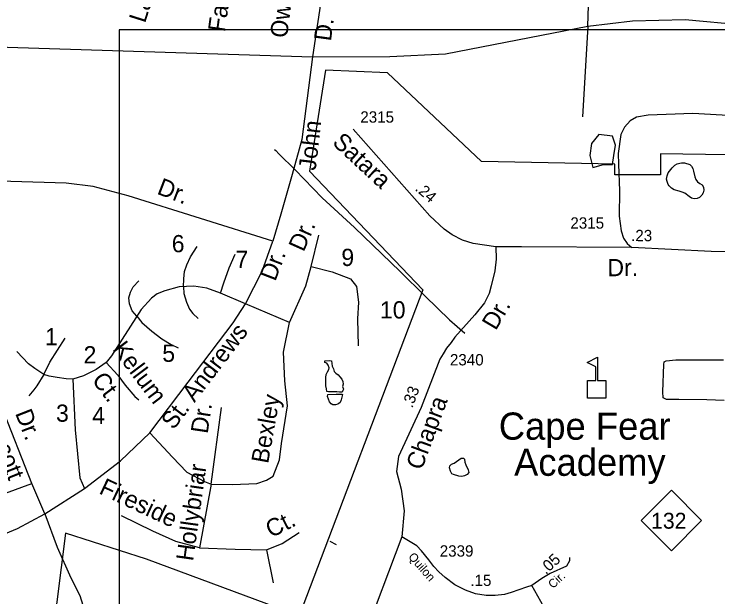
# Model space of a CAD drawing. Extents: x 2290055 to 2389491, y 66597 to 237875.
# Drawn here: x 2331332 to 2335214, y 153632 to 156845 of the extents above; entities that cross this region are included whole.
import ezdxf

# ---------------------------------------------------------------- set-up
doc = ezdxf.new("R2010")
doc.units = 0
for name, color, linetype in [('Exist Boundary Political City Limit New', 7, 'Continuous'), ('Exist Cultural Educational Facility Elementary CELL', 7, 'Continuous'), ('Exist Cultural Educational Facility Elementary Label', 7, 'Continuous'), ('Exist Hydrographic Pond Under 1500 Sq Ft', 7, 'Continuous'), ('Exist Road Non-System Type 51', 7, 'Continuous'), ('Exist Road Non-System Type 51 Label', 7, 'Continuous'), ('Exist Road Primary NC Shield CELL', 7, 'Continuous'), ('Exist Road Primary NC Shield Number Label', 7, 'Continuous'), ('Exist Road Secondary Mileage Hundredths English Label', 7, 'Continuous'), ('Exist Road Secondary Type 51 Attributed', 7, 'Continuous'), ('Exist Road Secondary Type 51 Label', 7, 'Continuous'), ('Exist Road Secondary Type 51 Number Label', 7, 'Continuous'), ('Map Preparation Boundary City Limit Buffer Line', 7, 'Continuous'), ('Map Preparation Inset Cut Line', 7, 'Continuous')]:
    doc.layers.add(name, color=color, linetype=linetype)

msp = doc.modelspace()

# ---------------------------------------------------------------- linework, layer by layer
at = {"layer": 'Exist Boundary Political City Limit New'}
msp.add_lwpolyline([(2335517.8, 156066.1), (2334898, 156075.8), (2334898, 155959.5), (2334646.2, 155959.5), (2334646.2, 156017.7), (2333910.5, 156032.2), (2333392.5, 156521.3), (2333049, 156535.9), (2332961.8, 155978.9), (2333586.2, 155325.1), (2332904, 153527.9), (2332062.8, 153841.3), (2331615.2, 153984.5), (2331473, 152848.5), (2331042.8, 151629.8), (2330040.5, 150815.1)], dxfattribs=at)
at = {"layer": 'Exist Cultural Educational Facility Elementary CELL'}
msp.add_lwpolyline([(2334494.6, 154727.8), (2334494.6, 154825.8), (2334540.6, 154825.8), (2334540.6, 154900.9), (2334493.6, 154925.1), (2334550.2, 154954.3), (2334550.2, 154825.8), (2334596.3, 154825.8), (2334596.3, 154727.8)], close=True, dxfattribs=at)
at = {"layer": 'Exist Hydrographic Pond Under 1500 Sq Ft'}
for points in [[(2334649.1, 156123.4), (2334632.6, 156173), (2334558.4, 156181.2), (2334517.1, 156131.7), (2334508.8, 156065.6), (2334525.3, 155999.5), (2334583.1, 156016), (2334632.6, 156016), (2334640.9, 156065.6), (2334649.1, 156123.4)], [(2335083.7, 155827.3), (2335069, 155831.2), (2335056, 155839.5), (2335032, 155858.6), (2335017.7, 155864.6), (2335000, 155869.9), (2334972.5, 155877.3), (2334958.2, 155884.9), (2334945, 155898.4), (2334939.7, 155906.1), (2334934.2, 155921.9), (2334931.5, 155935.8), (2334933.7, 155954.1), (2334940.2, 155969.4), (2334961.2, 155997.7), (2334976.7, 156011.7), (2334990.5, 156019.3), (2335004.2, 156023.8), (2335014.2, 156025.7), (2335030.2, 156024.7), (2335059.7, 156015.6), (2335069, 156007.8), (2335075.2, 155993.8), (2335080, 155978.9), (2335087.7, 155948.7), (2335093.5, 155934.1), (2335102.7, 155921.3), (2335114.5, 155911.6), (2335127.7, 155904.7), (2335135.5, 155891.3), (2335136, 155875.3), (2335132.2, 155860.3), (2335125.2, 155846.4), (2335113.2, 155835.1), (2335099.5, 155828.8), (2335083.7, 155827.3)], [(2333127, 154760.9), (2333112, 154762.7), (2333096.2, 154763), (2333066, 154762.3), (2333056.5, 154764.3), (2333055, 154780.1), (2333052.5, 154795.6), (2333051.2, 154826.8), (2333051.5, 154841.9), (2333053.2, 154857.8), (2333060, 154872.4), (2333068.2, 154885.4), (2333069.5, 154895.7), (2333064.5, 154910.2), (2333057, 154920.9), (2333046.7, 154924.2), (2333047, 154934), (2333074, 154935.7), (2333082.5, 154933.6), (2333085.5, 154918.7), (2333087, 154903.7), (2333093.7, 154889.2), (2333098, 154874.7), (2333106.7, 154865.8), (2333120, 154857.1), (2333129, 154844.8), (2333140, 154833.2), (2333146, 154820.1), (2333146.5, 154805.7), (2333144, 154793.1), (2333148.5, 154778.5), (2333145.7, 154769.4), (2333142.2, 154761.3), (2333127, 154760.9)], [(2333090.5, 154691), (2333080.5, 154697.4), (2333071.5, 154708.6), (2333061.7, 154737.6), (2333062.2, 154747.8), (2333108.7, 154749.5), (2333139.2, 154749.8), (2333144, 154748.6), (2333136.2, 154719.2), (2333131, 154705), (2333124.2, 154698.5), (2333117.2, 154694.6), (2333105.5, 154691.5), (2333090.5, 154691)], [(2333801, 154296.1), (2333785, 154298.5), (2333755.2, 154306.4), (2333746.7, 154310.6), (2333739, 154324.9), (2333733.5, 154343.2), (2333736.5, 154354.7), (2333745.7, 154364.1), (2333760, 154370.1), (2333784.7, 154388.8), (2333797.5, 154397), (2333811, 154398), (2333816.5, 154391.2), (2333818.7, 154375.8), (2333824.5, 154360.8), (2333837, 154332.5), (2333840.7, 154317.7), (2333830.5, 154306.4), (2333816.5, 154299.1), (2333801, 154296.1)]]:
    msp.add_lwpolyline(points, dxfattribs=at)
at = {"layer": 'Exist Road Non-System Type 51'}
for p, q in [((2332883.4, 155987.2), (2332793.2, 156075.3)), ((2333073.8, 153939.6), (2333109.2, 153921.2))]:
    msp.add_line(p, q, dxfattribs=at)
for points in [[(2329074.5, 157614.2), (2329735.5, 156994.4), (2329904, 156887), (2330064.9, 156787.4), (2330306.6, 156694.5), (2332978.6, 156610), (2333405, 156611), (2333711.5, 156626.4), (2334109.8, 156703), (2334497.5, 156778.2), (2334742.6, 156808.8), (2335033.7, 156816.5), (2335352.2, 156786.3)], [(2334497.5, 156778.2), (2334520.5, 157529.5)], [(2333057, 157134.9), (2332978.6, 156610), (2332918.7, 156153.4), (2332866.5, 155960.4), (2332804, 155743.1), (2332759.4, 155594.3), (2331962, 155844.3), (2331768.6, 155894.9), (2331619.9, 155912.8), (2331313.4, 155921.7), (2331161.7, 155930.7), (2331087.3, 155933.6), (2331012.9, 155972.3), (2330890.7, 156047.3), (2330775.5, 156052), (2330591.1, 155913.6), (2330489.7, 155821.3)], [(2334497.5, 156778.2), (2334466.8, 156279.9)], [(2335278.5, 156285.5), (2335238.5, 156288.1), (2335076, 156297.8), (2334928.2, 156291.9), (2334830.3, 156288), (2334764.7, 156277.6), (2334729.8, 156256.2), (2334698.9, 156222.8), (2334678.6, 156181.9), (2334664.6, 156077.3), (2334666.4, 156017.7)], [(2332768.7, 156098.4), (2332775.2, 156092.9), (2332793.2, 156075.3)], [(2334666.4, 156017.7), (2334670.8, 155871.8), (2334670.4, 155731.7), (2334681.5, 155650), (2334693.3, 155610.5), (2334714.5, 155581.4), (2334739.3, 155558.1)], [(2333599.2, 155291.2), (2333462, 155425.6), (2333360.2, 155523.6), (2333210.5, 155668), (2333031.7, 155832.9), (2332883.4, 155987.2)], [(2331501.7, 154089.6), (2331429.5, 154258), (2331261.8, 154683.9), (2331192.4, 154818.2), (2331128.2, 154906.2), (2330945.4, 155182.8), (2330734, 155541.8), (2330595.8, 155703.3), (2330489.7, 155821.3)], [(2332761.3, 154298.8), (2332796.6, 154388.6), (2332807, 154477.9), (2332839.7, 154686.3), (2332824.8, 154823.2), (2332818.9, 154981), (2332851.6, 155144.7), (2332940.9, 155347.2), (2332970.6, 155454.3), (2333012.3, 155627)], [(2330961.4, 153779.9), (2331082.5, 153881.8), (2331204.1, 153948.8), (2331351.6, 154008.7), (2331501.7, 154089.6), (2331719.9, 154230.2), (2331918.5, 154382.3), (2332081, 154537.4), (2332291.5, 154815.8), (2332539.9, 155143.3), (2332608.4, 155248.9), (2332699.9, 155427.6), (2332759.4, 155594.3)], [(2332266.4, 155342.5), (2332267.7, 155385.9), (2332272.2, 155426.1), (2332284.1, 155463.3), (2332304.9, 155506.4), (2332342.1, 155564.5)], [(2332471.5, 155307), (2332489.4, 155363.5), (2332519.1, 155446.9), (2332551.8, 155521.3)], [(2332970.6, 155454.3), (2333086.6, 155424.6), (2333187.8, 155385.9), (2333220.5, 155344.2), (2333232.4, 155257.9), (2333226.5, 155165.6), (2333229.4, 155016.7)], [(2332009.1, 155180.8), (2331983.6, 155210.2), (2331968.7, 155248.9), (2331965.7, 155281.7), (2331974.7, 155311.5), (2331988.1, 155342.7), (2332020.8, 155374)], [(2332608.4, 155248.9), (2332471.5, 155307), (2332395.7, 155335.3), (2332324.2, 155345.7), (2332242.4, 155341.2), (2332163.6, 155320.4), (2332121.9, 155302.5), (2332090.7, 155280.2), (2332032.7, 155217.7), (2331869, 154961.7), (2331839.3, 154924.4), (2331785.7, 154885.7), (2331714.3, 154851.5), (2331656.8, 154833.2), (2331619.1, 154835.1), (2331570.1, 154841.3), (2331525.4, 154850), (2331495.7, 154858.9), (2331446.3, 154891.1), (2331410.9, 154917), (2331346.8, 154986)], [(2332266.4, 155342.5), (2332269.2, 155305.5), (2332282.6, 155256.4), (2332299, 155219.2), (2332318.3, 155193.9), (2332348.1, 155167.1)], [(2333599.2, 155291.2), (2333734.7, 155160.3), (2333817.7, 155085.5)], [(2332851.6, 155144.7), (2332608.4, 155248.9)], [(2332009.1, 155180.8), (2332037.1, 155144.7), (2332092.2, 155097.1), (2332147.2, 155055.4), (2332197.8, 155024.2), (2332238, 155004.8)], [(2331495.7, 154858.9), (2331528.4, 154927.4), (2331614.7, 155058.4)], [(2331839.3, 154924.4), (2331904.7, 154854.5), (2331944.9, 154799.4), (2331998.5, 154736.9), (2332020.8, 154719)], [(2335248.6, 154715.9), (2335152.6, 154718.2), (2334998.6, 154720.3), (2334930.3, 154721.5), (2334911.9, 154730.7), (2334910.6, 154762.8), (2334916.8, 154913), (2334918.1, 154929.1), (2334928.1, 154933.5), (2334981.7, 154939.5), (2335178, 154939.4), (2335245.7, 154938.7)], [(2331495.7, 154858.9), (2331456.7, 154796.2), (2331440.5, 154774.2), (2331412.8, 154741.8)], [(2331656.8, 154833.2), (2331668.4, 154553.1), (2331695.6, 154289.2), (2331719.9, 154230.2)], [(2332081, 154537.4), (2332206, 154403.5), (2332284.8, 154320.1), (2332383, 154269.5), (2332418.7, 154254.6), (2332476.7, 154677.4)], [(2332418.7, 154254.6), (2332537.7, 154251.6), (2332671.6, 154257.6), (2332725.2, 154275.5), (2332761.3, 154298.8)], [(2331284.9, 154203.6), (2331429.5, 154258)], [(2332418.7, 154254.6), (2332355.2, 153903.3), (2332551, 153895.6), (2332723.9, 153891.8), (2332811.4, 153927.2), (2332904.9, 153987.5)], [(2331501.7, 154089.6), (2331569.5, 153907.3), (2331645.1, 153738.3), (2331694, 153640.5), (2331711.7, 153587.1), (2331739, 153488), (2331751.4, 153426), (2331762, 153367.5), (2331763.8, 153339.2), (2331762, 153296.7), (2331756.7, 153271.9), (2331730.2, 153186.8), (2331701.8, 153103.6), (2331684.1, 153039.8), (2331677, 152995.5), (2331668.2, 152930), (2331659.3, 152882.2), (2331650.5, 152845), (2331631, 152795.4), (2331608, 152724.5), (2331558.4, 152559.8), (2331459.3, 152251.6), (2331342.5, 151909.7)], [(2332355.2, 153903.3), (2332224.6, 153937.9), (2332097.8, 153995.5), (2331925, 154080.1)], [(2332723.9, 153891.8), (2332762, 153710.8)]]:
    msp.add_lwpolyline(points, dxfattribs=at)
at = {"layer": 'Exist Road Primary NC Shield CELL'}
msp.add_lwpolyline([(2334791.1, 154053.5), (2334957.6, 154220), (2335124.1, 154053.5), (2334957.6, 153887)], close=True, dxfattribs=at)
at = {"layer": 'Exist Road Secondary Type 51 Attributed'}
for points in [[(2333990.2, 155561.6), (2333865.1, 155581.5), (2333805.5, 155599.4), (2333747.9, 155628.2), (2333704.2, 155659), (2333625.3, 155734), (2333203.3, 156211.6)], [(2333990.2, 155561.6), (2333991.2, 155494.1), (2333984.3, 155430.5), (2333964.4, 155347), (2333953.5, 155304.3), (2333927.7, 155253.6), (2333874, 155187), (2333764.1, 155064), (2333742.3, 155034.2), (2333717.7, 155003.2), (2333698.7, 154971.9), (2333679.8, 154942.9), (2333577.1, 154676.9), (2333453.2, 154406.9), (2333440.9, 154324.3), (2333467.7, 154226), (2333483.3, 154106.1), (2333470.2, 153964.5)], [(2335340.8, 155534.1), (2335177.3, 155537.5), (2334739.3, 155558.1), (2334130.3, 155561.6), (2333990.2, 155561.6)], [(2333470.2, 153964.5), (2333256.2, 153394.6), (2333241.9, 153327.8), (2333251.3, 153238), (2333265.7, 153200.9), (2333285.2, 153167.9), (2333308.8, 153142.2), (2333369.7, 153092.9), (2333429.1, 153048.7), (2333475.8, 152991.2)], [(2334187.2, 153695.7), (2334158.8, 153686.2), (2334073.4, 153656.6), (2334037.3, 153646), (2333986.6, 153640.4), (2333936.9, 153640.4), (2333876.6, 153649.3), (2333821.4, 153670), (2333763.9, 153699), (2333710.5, 153739.1), (2333675.3, 153770.4), (2333647.5, 153800.5), (2333619.5, 153837.4), (2333579.6, 153886.9), (2333553.4, 153913.7), (2333470.2, 153964.5)], [(2334396.5, 153850.3), (2334396.5, 153830.4), (2334379.7, 153801), (2334288.7, 153761.3), (2334243.2, 153734.1), (2334187.2, 153695.7)], [(2335255.4, 152738.9), (2335203.9, 152740.1), (2335151, 152739.9), (2335104.2, 152743), (2335062.2, 152750.9), (2335006, 152765), (2334932.2, 152787.3), (2334841.5, 152822.5), (2334758.8, 152868.9), (2334643.4, 152962.4), (2334566, 153057.4), (2334525.5, 153118.1), (2334446.2, 153247.4), (2334364.9, 153386.8), (2334287.5, 153518.5), (2334187.2, 153695.7)]]:
    msp.add_lwpolyline(points, dxfattribs=at)
at = {"layer": 'Map Preparation Boundary City Limit Buffer Line'}
msp.add_lwpolyline([(2335517.8, 156066.1), (2334898, 156075.8), (2334898, 155959.5), (2334646.2, 155959.5), (2334646.2, 156017.7), (2333910.5, 156032.2), (2333392.5, 156521.3), (2333049, 156535.9), (2332961.8, 155978.9), (2333586.2, 155325.1), (2332904, 153527.9), (2332062.8, 153841.3), (2331615.2, 153984.5), (2331473, 152848.5), (2331042.8, 151629.8), (2330040.5, 150815.1)], dxfattribs=at)
at = {"layer": 'Map Preparation Inset Cut Line'}
msp.add_lwpolyline([(2325416.4, 141886.2), (2343900.4, 141886.2), (2346064.1, 148689.8), (2346393.7, 149726.2), (2346064.1, 149726.2), (2346064.1, 156758), (2331912.3, 156758), (2331912.3, 149726.2), (2325417.5, 149726.2)], close=True, dxfattribs=at)

# ---------------------------------------------------------------- texts
at = {"layer": 'Exist Cultural Educational Facility Elementary Label'}
for s, p in [('Cape Fear', (2334005.8, 154499)), ('Academy', (2334090, 154299.9))]:
    msp.add_text(s, height=150, dxfattribs=at).set_placement(p)
at = {"layer": 'Exist Road Non-System Type 51 Label'}
for s, rotation, p in [('Lawshe', 72.4593, (2332054.3, 156792)), ('Fairlie', 82.0691, (2332495, 156743.4)), ('Owens', 82.7784, (2332837.5, 156710.4)), ('D.', 82.2988, (2333079.6, 156692.9)), ('John', 83.441, (2332995.6, 155980.3)), ('Dr.', 338.9328, (2332115.3, 155855.9)), ('Dr.', 65.9936, (2332928.9, 155530.4)), ('Dr.', 68.9284, (2332772.6, 155368.3)), ('St. Andrews', 52.6456, (2332211.3, 154549.2)), ('Kellum', 307.0084, (2331871.1, 154997.6)), ('Ct.', 307.0084, (2331757.3, 154827.2)), ('Bexley', 79.9164, (2332733.2, 154363.9)), ('Prescott', 291.41, (2331133.8, 154702.4)), ('Dr.', 81.5558, (2332399.8, 154529)), ('Dr.', 291.3709, (2331336.6, 154645.2)), ('Hollybriar', 81.9793, (2332319.3, 153826.6)), ('Fireside', 334.8201, (2331795.4, 154204.6)), ('Ct.', 26.6522, (2332749.5, 153955.9))]:
    msp.add_text(s, height=95, rotation=rotation, dxfattribs=at).set_placement(p)
for s, p in [('6', (2332201.7, 155532.4)), ('7', (2332553.4, 155445.5)), ('9', (2333137.4, 155456.7)), ('10', (2333350.1, 155167.4)), ('1', (2331502.6, 155019.5)), ('2', (2331715.4, 154919.6)), ('5', (2332149.6, 154928.3)), ('3', (2331563.4, 154598)), ('4', (2331763.1, 154585))]:
    msp.add_text(s, height=95, dxfattribs=at).set_placement(p)
at = {"layer": 'Exist Road Primary NC Shield Number Label'}
msp.add_text('132', height=87.5, dxfattribs=at).set_placement((2334845.7, 154008.6))
at = {"layer": 'Exist Road Secondary Mileage Hundredths English Label'}
for s, rotation, p in [('.24', 318.6081, (2333540.3, 155877.4)), ('.23', 359.6579, (2334735.5, 155593.8)), ('.33', 69.3243, (2333528.7, 154670.6)), ('.05', 42.7772, (2334265.8, 153752.9)), ('.15', 0.3753, (2333849.1, 153692.2))]:
    msp.add_text(s, height=62.5, rotation=rotation, dxfattribs=at).set_placement(p)
at = {"layer": 'Exist Road Secondary Type 51 Label'}
for s, height, rotation, p in [('Satara', 95, 317.1421, (2333082.6, 156131.2)), ('Dr.', 95, 0.6591, (2334605.4, 155399.9)), ('Dr.', 95, 59.4119, (2333988.9, 155097)), ('Chapra', 95, 69.645, (2333580.1, 154326.5)), ('Quilon', 47.5, 311.3118, (2333503.2, 153851.6)), ('Cir.', 47.5, 42.7772, (2334304.6, 153675.4))]:
    msp.add_text(s, height=height, rotation=rotation, dxfattribs=at).set_placement(p)
at = {"layer": 'Exist Road Secondary Type 51 Number Label'}
for s, p in [('2315', (2333242, 156246.9)), ('2315', (2334400.6, 155662.5)), ('2340', (2333736.2, 154908.6)), ('2339', (2333680, 153854.4))]:
    msp.add_text(s, height=62.5, dxfattribs=at).set_placement(p)

doc.saveas('drawing.dxf')
